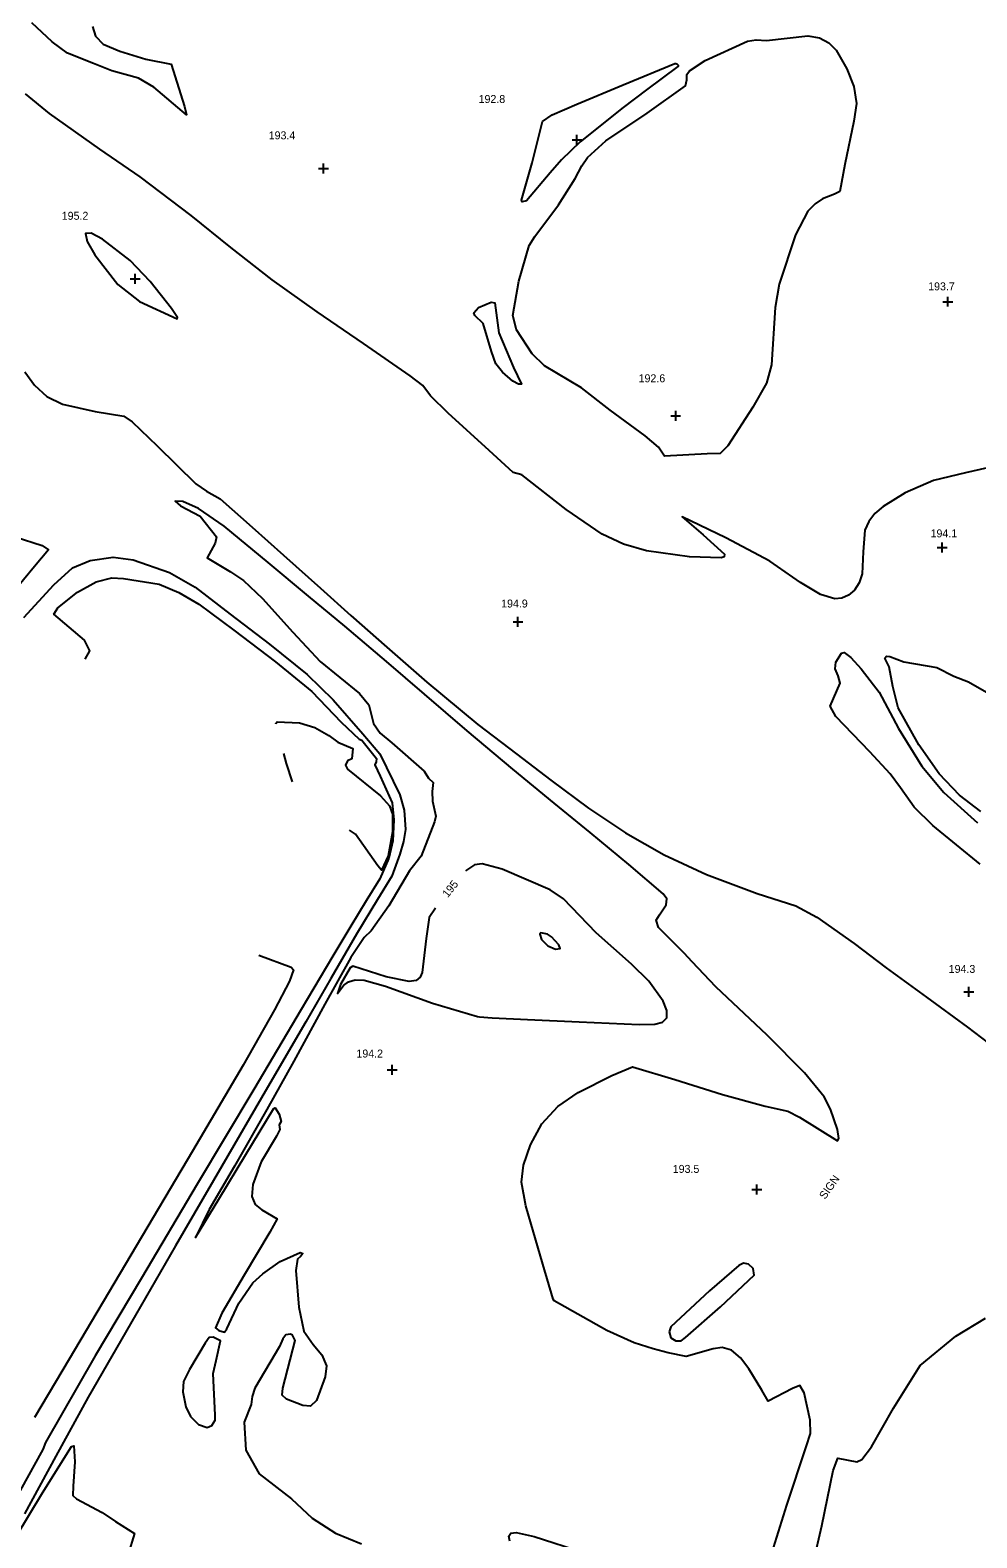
# Model space of a CAD drawing. Extents: x 1475150 to 2003689, y 770235 to 1112803.
# Drawn here: x 1993419.1 to 1993657.3, y 778214.1 to 778593.3 of the extents above; entities that cross this region are included whole.
import ezdxf

# ---------------------------------------------------------------- set-up
doc = ezdxf.new("R2010")
doc.units = 0
for name, color, linetype in [('RD_DTM_Major1', 7, 'Continuous'), ('RD_DTM_Major1_Lbl', 7, 'Continuous'), ('RD_DTM_Minor1', 7, 'Continuous'), ('RD_DTM_Spot_Elev', 7, 'Continuous'), ('RD_TX_Misc1', 7, 'Continuous')]:
    doc.layers.add(name, color=color, linetype=linetype)

msp = doc.modelspace()

# ---------------------------------------------------------------- linework, layer by layer
at = {"layer": 'RD_DTM_Major1'}
for points in [[(1993441.17, 778529.35), (1993446.59, 778525.08), (1993456.08, 778520.66), (1993456.15, 778520.99), (1993454.62, 778523.28), (1993449.27, 778530.09), (1993444.22, 778535.36), (1993437.27, 778540.75), (1993434.45, 778542.25), (1993433.01, 778542.17), (1993433.42, 778540.14), (1993435.32, 778536.77), (1993441.17, 778529.35)], [(1993521.1, 778372.46), (1993519.49, 778370.11), (1993518.72, 778364.83), (1993517.71, 778356.23), (1993517.2, 778355.07), (1993516.18, 778354.26), (1993514.42, 778353.97), (1993508.7, 778355.2), (1993500.3, 778357.84), (1993499.63, 778357.47), (1993497.18, 778353.26), (1993496.44, 778350.99), (1993497.92, 778353.01), (1993499.18, 778353.92), (1993500.9, 778354.41), (1993503.13, 778354.31), (1993508.47, 778352.85), (1993520.35, 778348.55), (1993531.66, 778345.18), (1993532.11, 778345.09), (1993535.33, 778344.83), (1993544.21, 778344.42), (1993557.2, 778343.84), (1993572.37, 778343.16), (1993576.31, 778343.24), (1993578.16, 778343.76), (1993579.28, 778344.86), (1993579.31, 778346.68), (1993578.38, 778349.02), (1993574.77, 778354.12), (1993570.36, 778358.38), (1993561.51, 778366.21), (1993553.27, 778374.8), (1993549.93, 778377.09), (1993537.84, 778382.23), (1993532.83, 778383.64), (1993530.88, 778383.37), (1993528.6, 778381.83)]]:
    msp.add_lwpolyline(points, dxfattribs=at)
at = {"layer": 'RD_DTM_Minor1'}
for points in [[(1993434.75, 778594.2), (1993435.53, 778591.76), (1993437.45, 778589.76), (1993441.64, 778588.02), (1993448.19, 778586.03), (1993454.54, 778584.73), (1993457.92, 778574.14), (1993458.4, 778571.97), (1993450.23, 778578.95), (1993446.32, 778581.25), (1993439.61, 778583.09), (1993435.04, 778584.91), (1993428.43, 778587.53), (1993424.63, 778590.37), (1993419.51, 778595.16)], [(1993565.07, 778497.69), (1993557.85, 778503.3), (1993548.52, 778508.86), (1993545.39, 778511.88), (1993541.5, 778517.94), (1993540.5, 778521.55), (1993542.02, 778530.2), (1993544.66, 778539.16), (1993546.11, 778541.41), (1993552.01, 778549.33), (1993556.24, 778556.02), (1993557.9, 778559.14), (1993559.35, 778561.26), (1993563.95, 778565.46), (1993574.36, 778572.41), (1993583.95, 778579.29), (1993584.31, 778580.78), (1993584.36, 778582.14), (1993585, 778583.07), (1993588.94, 778585.69), (1993599.56, 778590.54), (1993601.74, 778590.88), (1993604.4, 778590.66), (1993614.79, 778591.87), (1993617.68, 778591.39), (1993620.04, 778590.12), (1993621.91, 778588.23), (1993624.59, 778583.59), (1993626.34, 778579.14), (1993627, 778574.88), (1993626.39, 778570.42), (1993624.09, 778559.51), (1993622.84, 778552.72), (1993621.47, 778552.02), (1993618.44, 778550.86), (1993616.6, 778549.63), (1993614.78, 778547.73), (1993611.71, 778541.85), (1993607.59, 778529.44), (1993606.54, 778523.5), (1993605.65, 778509.09), (1993604.37, 778504.49), (1993600.92, 778498.49), (1993594.62, 778488.78), (1993592.7, 778486.81), (1993589.46, 778486.74), (1993578.73, 778486.13), (1993577.17, 778488.42), (1993573.8, 778491.25), (1993565.07, 778497.69)], [(1993568.34, 778573.84), (1993557.51, 778565.23), (1993552.77, 778560.71), (1993549.91, 778557.41), (1993543.98, 778550.35), (1993542.85, 778550.14), (1993542.75, 778550.54), (1993545.38, 778559.89), (1993548.02, 778570.3), (1993550.45, 778572.02), (1993556.63, 778574.7), (1993568.29, 778579.53), (1993581.33, 778584.93), (1993581.53, 778584.89), (1993581.79, 778584.82), (1993582, 778584.67), (1993582.12, 778584.46), (1993582.15, 778584.3), (1993582.11, 778584.19), (1993582.04, 778584.12), (1993574.18, 778578.27), (1993568.34, 778573.84)], [(1993661.81, 778483.66), (1993654.44, 778481.97), (1993646.42, 778480.06), (1993639.29, 778476.91), (1993633.7, 778473.46), (1993631.62, 778471.69), (1993630.09, 778469.74), (1993629.14, 778467.49), (1993628.7, 778462.05), (1993628.42, 778456.57), (1993627.68, 778454.29), (1993626.52, 778452.47), (1993625.05, 778451.16), (1993623.37, 778450.42), (1993621.6, 778450.28), (1993617.96, 778451.34), (1993612.92, 778454.37), (1993605.23, 778459.7), (1993594.14, 778465.56), (1993583.17, 778470.9), (1993588.43, 778466.39), (1993593.81, 778461.51), (1993593.72, 778460.79), (1993592.98, 778460.58), (1993585.03, 778460.82), (1993574.18, 778462.31), (1993568.39, 778464.02), (1993562.99, 778466.55), (1993553.93, 778472.72), (1993542.77, 778481.47), (1993540.58, 778482.07), (1993534.55, 778487.58), (1993524.28, 778496.95), (1993519.81, 778501.36), (1993517.87, 778503.94), (1993514.74, 778506.38), (1993502.92, 778514.45), (1993491.31, 778522.43), (1993479.94, 778530.46), (1993469.55, 778538.67), (1993459.58, 778546.66), (1993446.77, 778556.38), (1993436.58, 778563.4), (1993423.9, 778572.32), (1993417.94, 778577.32)], [(1993537.9, 778507.26), (1993536.22, 778509.37), (1993535.17, 778512.43), (1993533.07, 778519.51), (1993530.96, 778521.51), (1993530.76, 778522.22), (1993531.89, 778523.53), (1993535.11, 778524.85), (1993535.98, 778524.72), (1993537.02, 778517.16), (1993540.67, 778508.42), (1993542.75, 778504.28), (1993542, 778504.23), (1993540.53, 778505.02), (1993537.9, 778507.26)], [(1993417.76, 778507.36), (1993420.16, 778503.98), (1993423.29, 778501.13), (1993427.17, 778499.19), (1993435.45, 778497.36), (1993442.64, 778496.17), (1993444.73, 778494.8), (1993451.02, 778488.74), (1993460.73, 778479.2), (1993463.41, 778477.3), (1993466.92, 778475.38), (1993474.97, 778468.26), (1993482.85, 778461.23), (1993492.15, 778452.92), (1993499.81, 778446.07), (1993508.83, 778438.08), (1993518.87, 778429.33), (1993531.7, 778418.66), (1993541.57, 778411.17), (1993550.08, 778404.68), (1993559.59, 778397.64), (1993568.9, 778391.39), (1993578.64, 778385.87), (1993589.25, 778380.92), (1993602.06, 778376.14), (1993611.77, 778373.02), (1993617.06, 778370.15), (1993626.4, 778363.57), (1993634.48, 778357.47), (1993644.63, 778350.07), (1993654.99, 778342.55), (1993667.32, 778333.15)], [(1993606.14, 778211.54), (1993609.53, 778222.24), (1993614.36, 778236.96), (1993615.41, 778240.28), (1993615.4, 778243.62), (1993613.87, 778250.54), (1993612.78, 778252.4), (1993610.88, 778251.59), (1993604.83, 778248.47), (1993603.22, 778251.19), (1993599.95, 778256.59), (1993597.82, 778259.31), (1993595.53, 778261.23), (1993593.23, 778261.91), (1993590.99, 778261.64), (1993584.19, 778259.66), (1993579.65, 778260.62), (1993575.83, 778261.63), (1993571.03, 778263.1), (1993564.21, 778266.19), (1993550.98, 778273.67), (1993550.72, 778274.1), (1993548.06, 778282.92), (1993543.8, 778297.55), (1993542.69, 778303.54), (1993543.21, 778307.77), (1993544.96, 778312.89), (1993547.86, 778318.2), (1993551.89, 778322.52), (1993557.02, 778326.04), (1993565.47, 778330.38), (1993570.69, 778332.55), (1993581.29, 778329.32), (1993593.34, 778325.56), (1993604, 778322.63), (1993609.77, 778321.36), (1993612.7, 778319.88), (1993622.24, 778313.92), (1993622.57, 778314.52), (1993622.27, 778316.76), (1993620.49, 778321.88), (1993618.86, 778324.95), (1993613.95, 778331.01), (1993604.51, 778340.49), (1993591.62, 778352.68), (1993585.63, 778358.94), (1993583.69, 778361.12), (1993577.2, 778367.61), (1993576.59, 778369.42), (1993577.41, 778370.78), (1993579.14, 778373.25), (1993579.31, 778374.76), (1993578.38, 778376.05), (1993569.76, 778383.44), (1993560.01, 778391.48), (1993550.96, 778398.89), (1993540.55, 778407.42), (1993529.05, 778417.03), (1993518.35, 778426.25), (1993508.77, 778434.53), (1993498.3, 778443.35), (1993489.15, 778450.92), (1993478.95, 778459.36), (1993467.92, 778468.52), (1993461.45, 778473), (1993457.49, 778474.71), (1993455.6, 778474.83), (1993456.9, 778473.65), (1993461.89, 778471.03), (1993465.94, 778465.83), (1993465.61, 778464.24), (1993463.58, 778460.53), (1993469.51, 778457.04), (1993472.73, 778454.9), (1993477.58, 778450.32), (1993485.17, 778441.9), (1993492.09, 778434.46), (1993501.91, 778426.41), (1993504.32, 778423.61), (1993504.78, 778421.59), (1993505.45, 778418.87), (1993507.16, 778416.47), (1993510.08, 778414.02), (1993518.19, 778406.92), (1993519.34, 778405.12), (1993520.46, 778404.07), (1993520.22, 778401.83), (1993520.34, 778399.36), (1993521.12, 778395.63), (1993520.81, 778394.13), (1993517.45, 778385.53), (1993514.54, 778381.85), (1993509.36, 778373), (1993504.85, 778366.74), (1993503.14, 778365.07), (1993499.75, 778360.01), (1993493.2, 778348.29), (1993485.42, 778333.97), (1993478.65, 778321.8), (1993470.49, 778307.59), (1993464.16, 778296.61), (1993460.69, 778289.62), (1993466.59, 778299.24), (1993473.37, 778310.47), (1993480.3, 778322.01), (1993480.77, 778322.22), (1993481.77, 778320.62), (1993482.25, 778318.79), (1993481.77, 778317.94), (1993481.9, 778316.74), (1993481.08, 778315.11), (1993477.23, 778308.61), (1993475.1, 778302.92), (1993474.83, 778299.89), (1993475.68, 778297.93), (1993477.34, 778296.58), (1993481.22, 778294.28), (1993479.36, 778290.92), (1993472.96, 778280.11), (1993467.32, 778270.57), (1993465.69, 778266.91), (1993466.55, 778266.23), (1993468.01, 778265.8), (1993468.54, 778266.65), (1993471.56, 778273.07), (1993475.14, 778278.22), (1993477.63, 778280.48), (1993481.96, 778283.59), (1993486.99, 778285.8), (1993487.68, 778285.61), (1993487.13, 778284.83), (1993486.39, 778284.14), (1993485.91, 778281.29), (1993486.69, 778272.08), (1993487.95, 778266.02), (1993490.25, 778262.65), (1993492.46, 778260.1), (1993493.62, 778257.33), (1993493.3, 778254.53), (1993491.17, 778248.59), (1993489.63, 778247.17), (1993487.71, 778247.32), (1993483.56, 778248.96), (1993482.51, 778249.98), (1993482.63, 778251.67), (1993485.72, 778263.66), (1993485.07, 778265.02), (1993484.62, 778265.25)], [(1993415.26, 778465.86), (1993422.08, 778463.64), (1993423.66, 778462.55), (1993420.19, 778458.4), (1993411.88, 778448.31)], [(1993417.44, 778445.55), (1993425.01, 778453.81), (1993429.76, 778458.07), (1993434.18, 778459.93), (1993439.95, 778460.72), (1993444.98, 778460.1), (1993454.1, 778456.88), (1993460.61, 778453.16), (1993469.43, 778446.4), (1993479.32, 778438.86), (1993488.81, 778431.2), (1993495.3, 778424.83), (1993502.81, 778416.28), (1993507.1, 778411.28), (1993512.1, 778400.95), (1993513.2, 778397.12), (1993513.49, 778392.21), (1993513.01, 778389.24), (1993512.1, 778386.03), (1993510.06, 778380.51), (1993506.48, 778374.59), (1993501.18, 778365.92), (1993494.76, 778354.77), (1993488.41, 778343.83), (1993478.81, 778327.35), (1993467.3, 778307.57), (1993455.63, 778287.48), (1993445.56, 778270.11), (1993433.71, 778249.47), (1993425.57, 778234.6), (1993417.64, 778220.06)], [(1993432.93, 778435.04), (1993434.06, 778437.21), (1993432.71, 778439.87), (1993425.03, 778446.41), (1993426.02, 778447.99), (1993430.99, 778451.91), (1993435.71, 778454.5), (1993439.61, 778455.51), (1993442.57, 778455.39), (1993451.56, 778453.98), (1993456.49, 778451.86), (1993461.52, 778448.92), (1993470.3, 778442.35), (1993480.84, 778434.43), (1993489.98, 778426.95), (1993497.33, 778419.26), (1993501.89, 778414.98), (1993502.51, 778414.68), (1993506.24, 778410.11), (1993506.15, 778409.22), (1993505.84, 778408.5), (1993507.15, 778405.67), (1993510.16, 778398.97), (1993510.61, 778394.7), (1993510.33, 778389.36), (1993509.34, 778385), (1993507.09, 778379.81), (1993503.63, 778374.33), (1993499.77, 778367.94), (1993495.26, 778360.35), (1993487.29, 778346.97), (1993475.32, 778326.87), (1993461.14, 778303.03), (1993447.07, 778279.38), (1993435.47, 778259.86), (1993422.97, 778238.08), (1993422.3, 778236.31), (1993416.54, 778225.94)], [(1993658.18, 778383.53), (1993646.2, 778393.24), (1993641.52, 778397.82), (1993638.07, 778402.72), (1993635.48, 778406.2), (1993630.35, 778411.73), (1993621.79, 778420.62), (1993620.36, 778423.29), (1993622.91, 778429.08), (1993622.37, 778430.85), (1993621.66, 778432.64), (1993621.83, 778434.29), (1993623.24, 778436.6), (1993623.89, 778436.76), (1993625.58, 778435.51), (1993628.21, 778432.68), (1993632.69, 778426.82), (1993637.61, 778417.61), (1993643.5, 778408.19), (1993648.98, 778401.57), (1993657.5, 778393.87)], [(1993658.28, 778396.73), (1993652.97, 778400.9), (1993647.84, 778406.23), (1993642.75, 778413.53), (1993637.53, 778422.88), (1993636.14, 778428.17), (1993635.24, 778433.19), (1993634.8, 778433.96), (1993634.12, 778435.34), (1993634.54, 778435.81), (1993635.44, 778435.78), (1993638.96, 778434.41), (1993647.24, 778432.99), (1993651.49, 778430.79), (1993655.18, 778429.35), (1993663.81, 778424.4)], [(1993480.88, 778418.85), (1993480.87, 778418.87), (1993481.26, 778419.33), (1993486.81, 778419.06), (1993490.74, 778417.93), (1993494.22, 778415.92), (1993496.49, 778414.23), (1993500.31, 778412.64), (1993500, 778410.01), (1993498.91, 778409.5), (1993498.4, 778408.41), (1993498.92, 778407.42), (1993507.2, 778400.69), (1993509.48, 778398.15), (1993510.24, 778396.07), (1993510.24, 778391.66), (1993509.13, 778385.65), (1993507.5, 778381.99), (1993506.55, 778383.1), (1993500.93, 778391.07), (1993499.47, 778392.1)], [(1993485.07, 778404.26), (1993483.6, 778408.83), (1993482.91, 778411.35)], [(1993550.3, 778365.21), (1993549.29, 778365.92), (1993547.57, 778366.21), (1993547.3, 778365.93), (1993547.79, 778364.58), (1993549.32, 778363.01), (1993551.25, 778362.15), (1993552.45, 778362.27), (1993552.1, 778363.26), (1993550.3, 778365.21)], [(1993476.58, 778360.63), (1993484.75, 778357.59), (1993485.31, 778356.93), (1993484.37, 778354.11), (1993480.59, 778346.87), (1993472.67, 778332.97), (1993459.93, 778311.29), (1993444.42, 778285.14), (1993428.85, 778258.97), (1993420.16, 778244.36)], [(1993579.84, 778265.85), (1993580.31, 778264.4), (1993581.52, 778263.63), (1993582.86, 778263.61), (1993583.99, 778264.46), (1993592.8, 778272.14), (1993601.3, 778280.1), (1993600.99, 778281.81), (1993599.86, 778282.87), (1993598.59, 778283.13), (1993597.43, 778282.6), (1993590.03, 778276.2), (1993580.27, 778267.13), (1993579.84, 778265.85)], [(1993616.21, 778208.03), (1993618.32, 778217.06), (1993621.19, 778231.01), (1993622.36, 778234.14), (1993627.09, 778233.14), (1993628.4, 778233.78), (1993630.79, 778236.97), (1993636.35, 778246.65), (1993643.07, 778257.37), (1993652.04, 778264.81), (1993659.45, 778269.28)], [(1993465.64, 778244.88), (1993465.14, 778255.37), (1993465.84, 778258.69), (1993466.93, 778263.59), (1993465.09, 778264.56), (1993464.13, 778264.43), (1993463.13, 778263.02), (1993459.2, 778256.44), (1993457.7, 778253.37), (1993457.52, 778250.76), (1993458.21, 778246.99), (1993459.46, 778244.58), (1993461.41, 778242.6), (1993463.59, 778241.85), (1993464.79, 778242.35), (1993465.61, 778243.66), (1993465.64, 778244.88)], [(1993484.62, 778265.25), (1993483.42, 778265.15), (1993482.66, 778264.12), (1993481.83, 778262.23), (1993475.58, 778251.73), (1993474.92, 778249.57), (1993474.72, 778247.57), (1993472.93, 778243.12), (1993473.37, 778236.08), (1993476.67, 778230.18), (1993484.8, 778223.91), (1993490.08, 778219.02), (1993495.94, 778215.24), (1993502.42, 778212.51)], [(1993415.53, 778214.36), (1993422.21, 778225.34), (1993429.51, 778237.07), (1993430.05, 778237.21), (1993430.3, 778233.14), (1993429.9, 778227.07), (1993429.84, 778224.71), (1993430.75, 778223.89), (1993437.19, 778220.46), (1993440.53, 778218.21), (1993445.33, 778215.11), (1993443.71, 778209.93)], [(1993539.77, 778213.26), (1993539.51, 778214.5), (1993540.03, 778215.26), (1993541.36, 778215.42), (1993545.91, 778214.37), (1993558.43, 778210.4)]]:
    msp.add_lwpolyline(points, dxfattribs=at)
at = {"layer": 'RD_DTM_Spot_Elev'}
for p, q in [((1993556.68, 778564.48), (1993556.68, 778566.98)), ((1993555.43, 778565.73), (1993557.93, 778565.73)), ((1993492.89, 778557.25), (1993492.89, 778559.75)), ((1993491.64, 778558.5), (1993494.14, 778558.5)), ((1993444.23, 778530.72), (1993446.73, 778530.72)), ((1993445.48, 778529.47), (1993445.48, 778531.97)), ((1993648.75, 778525), (1993651.25, 778525)), ((1993650, 778523.75), (1993650, 778526.25)), ((1993580.27, 778496.27), (1993582.77, 778496.27)), ((1993581.52, 778495.02), (1993581.52, 778497.52)), ((1993648.59, 778461.92), (1993648.59, 778464.42)), ((1993647.34, 778463.17), (1993649.84, 778463.17)), ((1993541.83, 778443.25), (1993541.83, 778445.75)), ((1993540.58, 778444.5), (1993543.08, 778444.5)), ((1993654.06, 778351.41), (1993656.56, 778351.41)), ((1993655.31, 778350.16), (1993655.31, 778352.66)), ((1993508.94, 778331.81), (1993511.44, 778331.81)), ((1993510.19, 778330.56), (1993510.19, 778333.06)), ((1993600.71, 778301.67), (1993603.21, 778301.67)), ((1993601.96, 778300.42), (1993601.96, 778302.92))]:
    msp.add_line(p, q, dxfattribs=at)

# ---------------------------------------------------------------- texts
at = {"layer": 'RD_DTM_Major1_Lbl'}
msp.add_text('195', height=2, rotation=51.2187, dxfattribs=at).set_placement((1993524.16, 778374.96))
at = {"layer": 'RD_DTM_Spot_Elev'}
for s, p in [('192.8', (1993531.92, 778574.98)), ('193.4', (1993479.1, 778565.84)), ('195.2', (1993427.02, 778545.61)), ('193.7', (1993645.06, 778527.86)), ('192.6', (1993572.19, 778504.73)), ('194.1', (1993645.66, 778465.72)), ('194.9', (1993537.6, 778448.08)), ('194.3', (1993650.22, 778356.16)), ('194.2', (1993501.18, 778334.88)), ('193.5', (1993580.78, 778305.86))]:
    msp.add_text(s, height=2, dxfattribs=at).set_placement(p)
at = {"layer": 'RD_TX_Misc1'}
msp.add_text('SIGN', height=2, rotation=54.6599, dxfattribs=at).set_placement((1993619.1, 778299.05))

doc.saveas('drawing.dxf')
